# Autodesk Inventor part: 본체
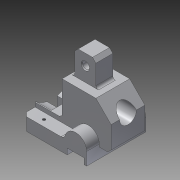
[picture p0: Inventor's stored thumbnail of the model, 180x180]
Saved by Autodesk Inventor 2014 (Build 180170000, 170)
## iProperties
Created: 2016-11
Part Number: 본체
Material: 알루미늄 6061
Document SubType Name: Modeling
Designer: USER
Mass: 462.906 g
Surface Area: 317.29 cm^2
Volume: 170.814 cm^3
Density: 2.71 g/cm^3
Appearance: 알루미늄 - 평지
Author: USER
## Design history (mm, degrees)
sketch "스케치1"
  geometry: L1 (-13, 0)-(-13, -15); L2 (-13, -15)-(-10, -15); L3 (13, 0)-(-13, 0); L4 (-10, -15)-(-10, -8); L5 (-10, -8)-(10, -8); L6 (10, -8)-(10, -15); L7 (10, -15)-(63, -15); L8 (13, 0)-(63, 0); L9 (63, 0)-(63, -15); A1 r 13 centre (0, 0) between (13, 0) and (-13, 0); 1 further point
  constraints: 18 end point, 5 perpendicular, 3 parallel, 2 point on circle, 1 centre point, 1 coincident, 1 tangent, 1 vertical, 1 vertical alignment
  dimensions: "d0" = 26 diameter of A1; "d1" = 15 distance of L1.start L1.end; "d2" = 3 distance of L1.end L2.end; "d3" = 7 distance of L2.end L4.end; "d4" = 20 distance of L4.end L5.end; "d5" = 63 horizontal distance of L7.end point (0, 0); "d6" = 15 distance between parallel lines of L8 L7
extrude "돌출1" new body sketch "스케치1" stored distance "d7" = 70; taper "d8" = 0 deg
sketch "스케치3"
  geometry: L1 (13, 0)-(63, 0) reference; L2 (63, 0)-(63, -15) reference; L3 (63, -15)-(10, -15) reference; L4 (10, -15)-(10, -8) reference; L5 (10, -8)-(-10, -8) reference; L6 (-10, -8)-(-10, -15) reference; L7 (-10, -15)-(-13, -15) reference; L8 (-13, -15)-(-13, 0) reference; L9 (-27, -3)-(-27, 27); L10 (-27, 27)-(-9, 45); L11 (-27, 27)-(-1.544, 27); L12 (-27, -3)-(63, -3); L13 (63, 0)-(63, 5); L14 (63, -3)-(63, 0); L15 (-9, 45)-(31, 45); L16 (31, 45)-(31, 5); L17 (31, 5)-(63, 5); A1 r 13 centre (0, 0) between (13, 0) and (-13, 0) reference; 1 further point
  constraints: 18 end point, 5 perpendicular, 1 collinear, 1 equal length, 1 horizontal, 1 parallel, 1 point on line
  dimensions: "d25" = 30 distance of L9.start L9.end; "d27" = 45 deg angle of L11 L10; "d28" = 18 distance from line of L9 L10.end; "d29" = 60 distance from line of L3 L10.end; "d30" = 90 distance between parallel lines of L2 L9; "d31" = 5 distance of L1.end L13.end; "d32" = 58 distance from line of L9 L15.end
extrude "돌출3" join sketch "스케치3" stored distance "d33" = 40; taper "d34" = 0 deg
sketch "스케치4"
  geometry: L1 (-13, -3)-(-27, -3) reference; L2 (-27, -3)-(-27, 27) reference; L3 (-27, 27)-(-9, 45) reference; L4 (-9, 45)-(31, 45) reference; L5 (31, 45)-(31, 5) reference; L6 (31, 5)-(63, 5) reference; L7 (63, 5)-(63, -15) reference; L8 (63, -15)-(10, -15) reference; L9 (10, -15)-(10, -8) reference; L10 (10, -8)-(-10, -8) reference; L11 (-10, -8)-(-10, -15) reference; L12 (-10, -15)-(-13, -15) reference; L13 (-13, -15)-(-13, -3) reference; L14 (26, 45)-(26, 75); L15 (26, 75)-(1, 75); L16 (1, 75)-(1, 45); L17 (26, 45)-(1, 45); 1 further point
  constraints: 8 end point, 2 perpendicular, 2 point on line, 1 collinear, 1 horizontal alignment, 1 parallel
  dimensions: "d35" = 90 distance from line of L8 L14.end; "d36" = 5 distance between parallel lines of L5 L14; "d37" = 25 distance of L14.end L15.end
extrude "돌출4" join sketch "스케치4" stored distance "d38" = 20; taper "d39" = 0 deg
sketch "스케치5"
  geometry: L1 (0, 0)-(-40, 0) reference; L2 (-40, 0)-(-45, 0) reference; L3 (-45, 0)-(-45, -15) reference; L4 (-45, -15)-(-60, -15) reference; L5 (-60, -15)-(-60, 55) reference; L6 (-60, 55)-(-45, 55) reference; L7 (-45, 55)-(-45, 40) reference; L8 (-45, 40)-(-40, 40) reference; L9 (-40, 40)-(0, 40) reference; L10 (0, 40)-(0, 0) reference; L11 (-40, 40)-(-40, 0) reference; C1 r 14.5 at (-18, 20); 1 further point
  constraints: 1 centre point, 1 horizontal alignment
  dimensions: "d40" = 29 diameter of C1; "d41" = 42 distance from line of L5 C1.centre
extrude "돌출5" cut sketch "스케치5" distance "d42" = 7; taper "d43" = 0 deg
sketch "스케치6"
  geometry: C1 r 14.5 at (0, 0) reference; C2 r 10 at (0, 0); 1 further point
  constraints: 1 centre point, 1 coincident
  dimensions: "d44" = 20 diameter of C2
extrude "돌출6" cut sketch "스케치6" stored distance "d45" = 7; taper "d46" = 0 deg
sketch "스케치7"
  geometry: L1 (20, 15)-(15, 15) reference; L2 (15, 15)-(15, 0) reference; L3 (15, 0)-(0, 0) reference; L4 (0, 0)-(0, 70) reference; L5 (0, 70)-(15, 70) reference; L6 (15, 70)-(15, 55) reference; L7 (15, 55)-(20, 55) reference; L8 (20, 55)-(20, 15) reference; L9 (20, 16.106)-(20, 53.894); C1 r 10 at (42, 35) reference; A1 r 29 centre (42, 35) between (20, 53.894) and (20, 16.106); 1 further point
  constraints: 2 end point, 2 point on circle, 2 point on line, 1 centre point, 1 coincident
  dimensions: "d47" = 58 diameter of A1
extrude "돌출7" cut sketch "스케치7" distance "d48" = 18; taper "d49" = 0 deg
sketch "스케치8"
  geometry: L1 (0, 70)-(0, 0) reference; L2 (30, 41)-(0, 41); L3 (0, 41)-(0, 29); L4 (0, 29)-(30, 29); L5 (30, 29)-(30, 41); 2 further points
  constraints: 8 end point, 2 midpoint, 2 parallel, 1 horizontal, 1 perpendicular
  dimensions: "d50" = 12 distance of L2.end L3.end; "d51" = 30 distance of L3.end L4.end
extrude "돌출8" cut sketch "스케치8" distance "d52" = 18; taper "d53" = 0 deg
sketch "스케치10"
  geometry: L1 (0, 0)-(0, -15) reference; L2 (50, -55)-(0, -55) reference; L3 (0, -70)-(0, -55) reference; L4 (50, -70)-(0, -70) reference; L5 (76, -70)-(50, -70) reference; L6 (76, -55)-(76, -70) reference; L7 (90, -55)-(76, -55) reference; L8 (90, -15)-(90, -55) reference; L9 (76, -15)-(90, -15) reference; L10 (76, 0)-(76, -15) reference; L11 (50, 0)-(76, 0) reference; L12 (50, -15)-(50, 0) reference; L13 (0, -15)-(50, -15) reference; L14 (0, -24.417)-(0, -15) reference; L15 (18, -24.417)-(0, -24.417) reference; L16 (18, -45.583)-(18, -24.417) reference; L17 (0, -45.583)-(18, -45.583) reference; L18 (0, -55)-(0, -45.583) reference; L19 (50, -70)-(50, -55) reference; L20 (0, 0)-(50, 0) reference; L21 (0, -15)-(0, 0) reference; L22 (90, -35)-(0, -35); 2 further points
  constraints: 2 end point, 1 midpoint, 1 perpendicular
  dimensions: "d58" = 27.5 distance from line of L22 point (18, -7.5); "d59" = 18 distance from line of L1 point (18, -7.5)
hole "구멍1" sketch "스케치10" at (18, -7.5) diameter "d60" = 3.242; stored, may be unused: countersink angle "d64" = 90 deg, drill point angle "d66" = 118 deg; dims "d61" = 6, "d62" = 4, "d63" = 2, "d65" = 8
sketch "스케치11"
  geometry: L1 (-26, -75)-(-1, -75) reference; L2 (-63, 15)-(-10, 15) reference; C1 r 4 at (-13.5, -62); 2 further points
  constraints: 1 centre point, 1 midpoint, 1 vertical alignment
  dimensions: "d67" = 8 diameter of C1; "d68" = 77 distance from line of L2 C1.centre
extrude "돌출10" cut sketch "스케치11" stored distance "d69" = 18; taper "d70" = 0 deg
sketch "스케치12"
  geometry: L1 (-31, -5)-(-31, -45) reference; L2 (-31, -45)-(9, -45) reference; 1 further point
  constraints: 1 other
  dimensions: "d71" = 25 distance from line of L1 point (-6, -27); "d72" = 18 distance from line of L2 point (-6, -27)
feature "엠보싱1" sketch "스케치12" dims "d0" = 26, "d1" = 15, "d2" = 3, "d3" = 7, "d4" = 20, "d5" = 63, "d6" = 15, "d25" = 30, "d27" = 45 deg, "d28" = 18, "d29" = 60, "d30" = 90, "d31" = 5, "d32" = 58, "d73" = 0.5, "d74" = 0
chamfer "모따기1" distance "d75" = 5; stored, may be unused: second distance "d76" = 2, angle "d77" = 45 deg
chamfer "모따기2" distance "d78" = 4; stored, may be unused: second distance "d79" = 2, angle "d80" = 45 deg
chamfer "모따기3" distance "d81" = 1; stored, may be unused: second distance "d82" = 2, angle "d83" = 45 deg
fillet "모깎기1" dims "d84" = 5
fillet "모깎기2" dims "d85" = 3
node "솔리드1"
mirror "대칭1"
node "절단 모서리 투영2"
node "절단 모서리 투영3"
node "절단 모서리 투영4"
node "절단 모서리 투영5"
node "절단 모서리 투영6"
